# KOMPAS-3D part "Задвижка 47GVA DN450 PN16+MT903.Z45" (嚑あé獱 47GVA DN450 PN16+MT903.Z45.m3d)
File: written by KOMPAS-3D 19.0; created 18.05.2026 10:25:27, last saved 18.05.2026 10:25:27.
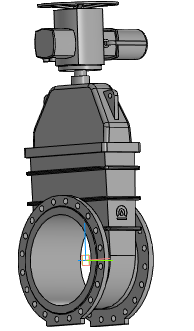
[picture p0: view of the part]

Document properties: Автор: Энергия; Полное имя файла: ..\Задвижка 47GVA DN50_DN1000+MT903.Z\Задвижка 47GVA DN450 PN16+MT903.Z45.a3d

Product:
- Part/product: Задвижка 47GVA DN450 PN16+MT903.Z45
    Масса: 845.17
  - Body: Электропривод MT903.Z45-60
      Масса: 170.293
  - Body: Задвижка 47GVA DN450 PN16 без исполнительного механизма
      Масса: 674.877

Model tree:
1. Операция без истории:1
2. Операция без истории:2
